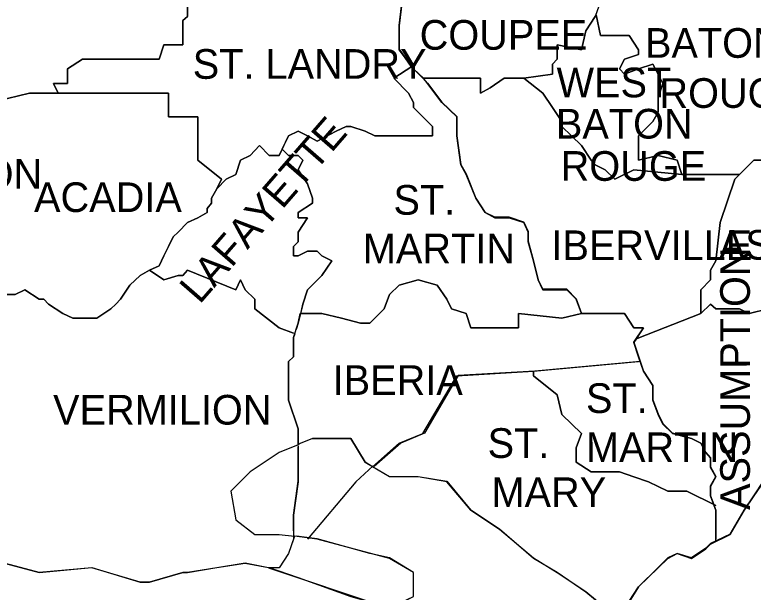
# Model space of a CAD drawing. Extents: x 0.19 to 2.82, y 0.04 to 1.79.
# Drawn here: x 2.3204 to 2.4368, y 1.4533 to 1.5443 of the extents above; entities that cross this region are included whole.
import ezdxf

# ---------------------------------------------------------------- set-up
doc = ezdxf.new("R2010")
doc.units = 0
for name, color, linetype in [('Dist02', 7, 'Continuous'), ('Dist03', 7, 'Continuous'), ('Dist61', 7, 'Continuous'), ('Standard Info', 7, 'Continuous')]:
    doc.layers.add(name, color=color, linetype=linetype)

msp = doc.modelspace()

# ---------------------------------------------------------------- linework, layer by layer
at = {"layer": 'Dist02'}
msp.add_lwpolyline([(2.4369, 1.4685), (2.4354, 1.46625), (2.43315, 1.4625), (2.43007, 1.461), (2.42932, 1.46025), (2.42707, 1.45875), (2.42482, 1.45942), (2.42332, 1.45875), (2.42182, 1.45725), (2.41874, 1.45417), (2.41724, 1.45192), (2.41799, 1.44967), (2.41799, 1.44817), (2.42032, 1.44508), (2.42182, 1.44358), (2.42182, 1.44208), (2.42099, 1.44133), (2.41949, 1.43983), (2.41799, 1.43825), (2.41574, 1.43492)], dxfattribs=at)
at = {"layer": 'Dist03'}
for points in [[(2.3829, 1.53617), (2.38099, 1.53892), (2.38099, 1.54267), (2.38165, 1.548), (2.38165, 1.551), (2.38099, 1.554), (2.37949, 1.55858), (2.3779, 1.56158), (2.37715, 1.56308)], [(2.40974, 1.49725), (2.4089, 1.49958), (2.4074, 1.50108), (2.40365, 1.50108), (2.4029, 1.50258), (2.40215, 1.50558), (2.40132, 1.50867), (2.40132, 1.51017), (2.40065, 1.51167), (2.39832, 1.51242), (2.39607, 1.51242), (2.39457, 1.51317), (2.39307, 1.51542), (2.39157, 1.51925), (2.39074, 1.52075), (2.39007, 1.52525), (2.39007, 1.52833), (2.38774, 1.53058), (2.38549, 1.53358), (2.38474, 1.53433)], [(2.41899, 1.48975), (2.41799, 1.49275), (2.41949, 1.495), (2.41799, 1.495), (2.41649, 1.49725), (2.40974, 1.49725)], [(2.43057, 1.46717), (2.43007, 1.4685), (2.43007, 1.47008), (2.4309, 1.47158), (2.43007, 1.47308), (2.43007, 1.47458), (2.42932, 1.47533), (2.42857, 1.47683), (2.42707, 1.47758), (2.42407, 1.47842), (2.42257, 1.47992), (2.42182, 1.48142), (2.42099, 1.48367), (2.42099, 1.48592), (2.41949, 1.48817), (2.41899, 1.48975)], [(2.36732, 1.47758), (2.3734, 1.47758), (2.37565, 1.47383), (2.37682, 1.47317)], [(2.36432, 1.463), (2.36432, 1.4655), (2.36507, 1.47083), (2.36507, 1.47608), (2.36507, 1.47625)], [(2.37682, 1.47317), (2.37949, 1.47158), (2.38399, 1.47158), (2.38849, 1.47083), (2.39232, 1.46625), (2.39682, 1.46325), (2.40215, 1.45875), (2.4059, 1.45642), (2.4104, 1.45342), (2.41499, 1.44967), (2.41649, 1.44817), (2.41724, 1.44358), (2.41499, 1.44133), (2.41424, 1.43675), (2.41574, 1.435)], [(2.4309, 1.46175), (2.4309, 1.46325), (2.4309, 1.46475), (2.4309, 1.46625), (2.43065, 1.46692)], [(2.36049, 1.45725), (2.36507, 1.45567), (2.3734, 1.45267), (2.37865, 1.45117), (2.38015, 1.45117), (2.38324, 1.45267), (2.38324, 1.45642), (2.37949, 1.45875), (2.3764, 1.45942), (2.36807, 1.46175), (2.36482, 1.46217)], [(2.41574, 1.435), (2.41799, 1.43825), (2.41949, 1.43983), (2.42099, 1.44133), (2.42182, 1.44208), (2.42182, 1.44358), (2.42032, 1.44508), (2.41799, 1.44817), (2.41799, 1.44967), (2.41724, 1.45192), (2.41874, 1.45417), (2.42182, 1.45725), (2.42332, 1.45875), (2.42482, 1.45942), (2.42707, 1.45875), (2.42932, 1.46025), (2.43007, 1.461), (2.43099, 1.46142)], [(2.31815, 1.45808), (2.32424, 1.45642), (2.33257, 1.45725), (2.34015, 1.45492), (2.34165, 1.45492), (2.3469, 1.45642), (2.34765, 1.45642)], [(2.34765, 1.45642), (2.35224, 1.45725), (2.35674, 1.45792), (2.3604, 1.45725)]]:
    msp.add_lwpolyline(points, dxfattribs=at)
at = {"layer": 'Dist61'}
for points in [[(2.37715, 1.56308), (2.3779, 1.56158), (2.37949, 1.55858), (2.38099, 1.554), (2.38165, 1.551), (2.38165, 1.548), (2.38099, 1.54267), (2.38099, 1.53892), (2.3829, 1.53617)], [(2.38299, 1.53617), (2.38324, 1.53583), (2.38482, 1.53433)], [(2.38474, 1.53433), (2.38549, 1.53358), (2.38774, 1.53058), (2.39007, 1.52833), (2.39007, 1.52525), (2.39074, 1.52075), (2.39157, 1.51925), (2.39307, 1.51542), (2.39457, 1.51317), (2.39607, 1.51242), (2.39832, 1.51242), (2.40065, 1.51167), (2.40132, 1.51017), (2.40132, 1.50867), (2.40215, 1.50558), (2.4029, 1.50258), (2.40365, 1.50108), (2.4074, 1.50108), (2.4089, 1.49958), (2.40974, 1.49725)], [(2.40974, 1.49725), (2.41649, 1.49725), (2.41799, 1.495), (2.41949, 1.495), (2.41799, 1.49275), (2.41899, 1.48975)], [(2.41899, 1.48975), (2.41949, 1.48817), (2.42099, 1.48592), (2.42099, 1.48367), (2.42182, 1.48142), (2.42257, 1.47992), (2.42407, 1.47842), (2.42707, 1.47758), (2.42857, 1.47683), (2.42932, 1.47533), (2.43007, 1.47458), (2.43007, 1.47308), (2.4309, 1.47158), (2.43007, 1.47008), (2.43007, 1.4685), (2.43057, 1.46717)], [(2.4309, 1.46133), (2.43315, 1.4625), (2.4354, 1.46625), (2.4369, 1.4685), (2.4384, 1.47083), (2.44065, 1.47458), (2.44215, 1.47683), (2.44215, 1.47908), (2.44299, 1.48067), (2.44524, 1.48292)], [(2.43065, 1.46692), (2.4309, 1.46625), (2.4309, 1.46475), (2.4309, 1.46325), (2.4309, 1.46175)]]:
    msp.add_lwpolyline(points, dxfattribs=at)
at = {"layer": 'Standard Info'}
for p, q in [((2.38482, 1.53433), (2.38474, 1.53433)), ((2.3654, 1.47675), (2.36507, 1.47658)), ((2.43057, 1.46717), (2.4309, 1.467)), ((2.4309, 1.46133), (2.4309, 1.46175))]:
    msp.add_line(p, q, dxfattribs=at)
for points in [[(2.3469, 1.56308), (2.3469, 1.5585), (2.34765, 1.55625), (2.34924, 1.5555), (2.35074, 1.5555), (2.35074, 1.54867), (2.3484, 1.54867), (2.3484, 1.54717), (2.34765, 1.54642), (2.34765, 1.54408), (2.3469, 1.54342), (2.3469, 1.53958), (2.3439, 1.53958), (2.34315, 1.53733), (2.33107, 1.53733), (2.32874, 1.53583), (2.32874, 1.5335), (2.32649, 1.5335), (2.32724, 1.532)], [(2.32724, 1.532), (2.32649, 1.5335), (2.32874, 1.5335), (2.32874, 1.53583), (2.33107, 1.53733), (2.34315, 1.53733), (2.3439, 1.53958), (2.3469, 1.53958), (2.3469, 1.54342), (2.34765, 1.54408), (2.34765, 1.54642), (2.3484, 1.54717), (2.3484, 1.54867), (2.35074, 1.54867), (2.35074, 1.5555), (2.34924, 1.5555), (2.34765, 1.55625), (2.3469, 1.5585), (2.3469, 1.56308)], [(2.37715, 1.56308), (2.3779, 1.5615), (2.37949, 1.5585), (2.38099, 1.554), (2.38165, 1.55092), (2.38165, 1.54792), (2.38099, 1.54258), (2.38099, 1.53883), (2.3829, 1.53617)], [(2.38474, 1.53433), (2.38324, 1.53583), (2.38099, 1.53883), (2.38099, 1.54258), (2.38165, 1.54792), (2.38165, 1.55092), (2.38099, 1.554), (2.37949, 1.5585), (2.3779, 1.5615), (2.37715, 1.56308)], [(2.41274, 1.54642), (2.4119, 1.54408), (2.4104, 1.54183), (2.40974, 1.53883), (2.4059, 1.53958), (2.4059, 1.53733), (2.40515, 1.53658), (2.40515, 1.535), (2.40065, 1.53433)], [(2.40065, 1.53433), (2.40515, 1.535), (2.40515, 1.53658), (2.4059, 1.53733), (2.4059, 1.53958), (2.40974, 1.53883), (2.4104, 1.54183), (2.4119, 1.54408), (2.41199, 1.54433)], [(2.41207, 1.54433), (2.41274, 1.54108), (2.41724, 1.54108), (2.41874, 1.53883), (2.41874, 1.53808), (2.41649, 1.53733), (2.41574, 1.53583), (2.41649, 1.535), (2.41874, 1.53583), (2.42099, 1.53658), (2.42182, 1.535), (2.42257, 1.5335), (2.42182, 1.53125), (2.42182, 1.529), (2.42099, 1.5275), (2.41874, 1.52525), (2.41874, 1.52442), (2.41874, 1.52292), (2.41874, 1.52142), (2.42182, 1.52217), (2.42482, 1.52142), (2.42557, 1.51917)], [(2.42557, 1.51917), (2.42482, 1.52142), (2.42182, 1.52217), (2.41874, 1.52142), (2.41874, 1.52292), (2.41874, 1.52442), (2.41874, 1.52525), (2.42099, 1.5275), (2.42182, 1.529), (2.42182, 1.53125), (2.42257, 1.5335), (2.42182, 1.535), (2.42099, 1.53658), (2.41874, 1.53583), (2.41649, 1.535), (2.41574, 1.53583), (2.41649, 1.53733), (2.41874, 1.53808), (2.41874, 1.53883), (2.41724, 1.54108), (2.41274, 1.54108), (2.41207, 1.54433)], [(2.38299, 1.53617), (2.38015, 1.53433), (2.38249, 1.532), (2.38324, 1.5305), (2.38324, 1.52975), (2.38549, 1.5275), (2.38624, 1.52675), (2.38624, 1.52525), (2.37715, 1.52525), (2.37565, 1.526), (2.3734, 1.52675), (2.37265, 1.52675), (2.37107, 1.526), (2.36807, 1.52442), (2.36657, 1.52525), (2.36507, 1.526), (2.36357, 1.52525), (2.36282, 1.52375), (2.36207, 1.52217), (2.36049, 1.52217), (2.35899, 1.52375), (2.35749, 1.52217), (2.35599, 1.52142), (2.35524, 1.51917), (2.35374, 1.51842), (2.35224, 1.51692)], [(2.36257, 1.52317), (2.36357, 1.52525), (2.36507, 1.526), (2.36657, 1.52525), (2.36807, 1.52442), (2.37107, 1.526), (2.37265, 1.52675), (2.3734, 1.52675), (2.37565, 1.526), (2.37715, 1.52525), (2.38624, 1.52525), (2.38624, 1.52675), (2.38549, 1.5275), (2.38324, 1.52975), (2.38324, 1.5305), (2.38249, 1.532), (2.38015, 1.53433), (2.38299, 1.53617)], [(2.38299, 1.53617), (2.38324, 1.53583), (2.38482, 1.53433)], [(2.38474, 1.53433), (2.38549, 1.5335), (2.38774, 1.5305), (2.39007, 1.52825), (2.39007, 1.52525), (2.39074, 1.52067), (2.39157, 1.51917), (2.39307, 1.51542), (2.39457, 1.51317), (2.39607, 1.51233), (2.39832, 1.51233), (2.40065, 1.51158), (2.40132, 1.51008), (2.40132, 1.50858), (2.40215, 1.50558), (2.4029, 1.50258), (2.40365, 1.501), (2.4074, 1.501), (2.4089, 1.4995), (2.40974, 1.49725)], [(2.40065, 1.53433), (2.39757, 1.53433), (2.39532, 1.53283), (2.39382, 1.532), (2.39382, 1.53433), (2.38474, 1.53433)], [(2.40065, 1.53433), (2.39757, 1.53433), (2.39532, 1.53283), (2.39382, 1.532), (2.39382, 1.53433), (2.38474, 1.53433)], [(2.38474, 1.53433), (2.39382, 1.53433), (2.39382, 1.532), (2.39532, 1.53283), (2.39757, 1.53433), (2.40065, 1.53433)], [(2.4184, 1.49333), (2.41949, 1.495), (2.41799, 1.495), (2.41649, 1.49725), (2.40974, 1.49725), (2.4089, 1.4995), (2.4074, 1.501), (2.40365, 1.501), (2.4029, 1.50258), (2.40215, 1.50558), (2.40132, 1.50858), (2.40132, 1.51008), (2.40065, 1.51158), (2.39832, 1.51233), (2.39607, 1.51233), (2.39457, 1.51317), (2.39307, 1.51542), (2.39157, 1.51917), (2.39074, 1.52067), (2.39007, 1.52525), (2.39007, 1.52825), (2.38774, 1.5305), (2.38549, 1.5335), (2.38482, 1.53433)], [(2.40065, 1.53433), (2.40365, 1.532), (2.40515, 1.52975), (2.40665, 1.5275), (2.40665, 1.52675), (2.40815, 1.52525), (2.40974, 1.52375), (2.41124, 1.52142), (2.4119, 1.52067), (2.41349, 1.51992), (2.41499, 1.51842), (2.41799, 1.51992), (2.42557, 1.51917)], [(2.43465, 1.51917), (2.42557, 1.51917), (2.41799, 1.51992), (2.41499, 1.51842), (2.41349, 1.51992), (2.4119, 1.52067), (2.41124, 1.52142), (2.40974, 1.52375), (2.40815, 1.52525), (2.40665, 1.52675), (2.40665, 1.5275), (2.40515, 1.52975), (2.40365, 1.532), (2.40065, 1.53433)], [(2.40065, 1.53433), (2.40365, 1.532), (2.40515, 1.52975), (2.40665, 1.5275), (2.40665, 1.52675), (2.40815, 1.52525), (2.40974, 1.52375), (2.41124, 1.52142), (2.4119, 1.52067), (2.41349, 1.51992), (2.41499, 1.51842), (2.41799, 1.51992), (2.42557, 1.51917), (2.43465, 1.51917)], [(2.32724, 1.532), (2.32274, 1.532), (2.31749, 1.53075)], [(2.31749, 1.53075), (2.32274, 1.532), (2.32799, 1.532), (2.34465, 1.532), (2.34465, 1.52825), (2.34924, 1.52825), (2.34924, 1.52142), (2.35299, 1.51842), (2.35224, 1.51692)], [(2.35224, 1.51692), (2.35299, 1.51842), (2.34924, 1.52142), (2.34924, 1.52825), (2.34465, 1.52825), (2.34465, 1.532), (2.32724, 1.532)], [(2.34165, 1.50408), (2.34315, 1.50475), (2.3439, 1.50633), (2.34465, 1.50783), (2.3454, 1.50933), (2.34615, 1.51008), (2.34765, 1.51158), (2.34924, 1.51233), (2.35074, 1.51317), (2.35074, 1.51383), (2.3514, 1.51467), (2.3514, 1.51542), (2.35224, 1.51692), (2.35374, 1.51842), (2.35524, 1.51917), (2.35599, 1.52142), (2.35749, 1.52217), (2.35899, 1.52375), (2.36049, 1.52217), (2.36207, 1.52217), (2.36257, 1.52317)], [(2.36257, 1.52317), (2.36357, 1.52217), (2.36507, 1.52217), (2.36582, 1.52142), (2.36507, 1.51992), (2.36657, 1.51767), (2.36732, 1.51542), (2.36732, 1.51467), (2.36507, 1.51317), (2.36507, 1.51233), (2.36657, 1.51233), (2.36507, 1.51008), (2.36507, 1.50858), (2.36432, 1.50783), (2.36432, 1.50633), (2.36507, 1.50633), (2.36657, 1.50708), (2.36807, 1.50708), (2.36882, 1.50633), (2.3704, 1.50558), (2.36882, 1.50325), (2.36657, 1.501), (2.36582, 1.49875), (2.36507, 1.49575), (2.36474, 1.49475)], [(2.36549, 1.49725), (2.36582, 1.49875), (2.36657, 1.501), (2.36882, 1.50325), (2.3704, 1.50558), (2.36882, 1.50633), (2.36807, 1.50708), (2.36657, 1.50708), (2.36507, 1.50633), (2.36432, 1.50633), (2.36432, 1.50783), (2.36507, 1.50858), (2.36507, 1.51008), (2.36657, 1.51233), (2.36507, 1.51233), (2.36507, 1.51317), (2.36732, 1.51467), (2.36732, 1.51542), (2.36657, 1.51767), (2.36507, 1.51992), (2.36582, 1.52142), (2.36507, 1.52217), (2.36357, 1.52217), (2.36257, 1.52317)], [(2.42857, 1.49725), (2.42857, 1.4995), (2.42857, 1.501), (2.43007, 1.50258), (2.43007, 1.50408), (2.4309, 1.50558), (2.43157, 1.51158), (2.4339, 1.51842), (2.4369, 1.52142), (2.44524, 1.52142)], [(2.44524, 1.52142), (2.4369, 1.52142), (2.43465, 1.51917)], [(2.43465, 1.51917), (2.42557, 1.51917)], [(2.43465, 1.51917), (2.4339, 1.51842), (2.43157, 1.51158), (2.4309, 1.50558), (2.43007, 1.50408), (2.43007, 1.50258), (2.42857, 1.501), (2.42857, 1.4995), (2.42857, 1.49725)], [(2.35224, 1.51692), (2.3514, 1.51542), (2.3514, 1.51467), (2.35074, 1.51383), (2.35074, 1.51317), (2.34924, 1.51233), (2.34765, 1.51158), (2.34615, 1.51008), (2.3454, 1.50933), (2.34465, 1.50783), (2.3439, 1.50633), (2.34315, 1.50475), (2.34165, 1.50408), (2.34015, 1.50325), (2.33857, 1.50175), (2.33707, 1.4995), (2.33632, 1.49875), (2.33557, 1.498), (2.33332, 1.4965), (2.33182, 1.4965), (2.32957, 1.4965), (2.32799, 1.49725), (2.32574, 1.49875), (2.32499, 1.4995), (2.32424, 1.4995), (2.32199, 1.501), (2.32049, 1.50025), (2.31765, 1.50025)], [(2.4634, 1.50633), (2.44524, 1.50258), (2.44215, 1.50258), (2.44215, 1.50025), (2.44149, 1.50025), (2.43915, 1.498), (2.43615, 1.49725), (2.43465, 1.498), (2.4339, 1.498), (2.4324, 1.498), (2.4309, 1.498), (2.43007, 1.49875), (2.42857, 1.49725)], [(2.31765, 1.50025), (2.32049, 1.50025), (2.32199, 1.501), (2.32424, 1.4995), (2.32499, 1.4995), (2.32574, 1.49875), (2.32799, 1.49725), (2.32957, 1.4965), (2.33182, 1.4965), (2.33332, 1.4965), (2.33557, 1.498), (2.33632, 1.49875), (2.33707, 1.4995), (2.33857, 1.50175), (2.34015, 1.50325), (2.34165, 1.50408)], [(2.34165, 1.50408), (2.3439, 1.50258), (2.34615, 1.50325), (2.3469, 1.50325), (2.34765, 1.50408), (2.35524, 1.501), (2.35599, 1.50258), (2.35674, 1.501), (2.35824, 1.4995), (2.35824, 1.498), (2.36207, 1.495), (2.36432, 1.49417)], [(2.36432, 1.49417), (2.36207, 1.495), (2.35824, 1.498), (2.35824, 1.4995), (2.35674, 1.501), (2.35599, 1.50258), (2.35524, 1.501), (2.34765, 1.50408), (2.3469, 1.50325), (2.34615, 1.50325), (2.3439, 1.50258), (2.34165, 1.50408)], [(2.36549, 1.49725), (2.36882, 1.49725), (2.3719, 1.4965), (2.3749, 1.49575), (2.3764, 1.49575), (2.3779, 1.49725), (2.37865, 1.498), (2.37949, 1.50025), (2.38099, 1.50175), (2.38399, 1.50258), (2.38699, 1.50175), (2.38849, 1.4995), (2.38924, 1.498), (2.39157, 1.49725), (2.39232, 1.495), (2.39982, 1.495), (2.39982, 1.49725), (2.40665, 1.4965), (2.40974, 1.49725)], [(2.40974, 1.49725), (2.40665, 1.4965), (2.39982, 1.49725), (2.39982, 1.495), (2.39232, 1.495), (2.39157, 1.49725), (2.38924, 1.498), (2.38849, 1.4995), (2.38699, 1.50175), (2.38399, 1.50258), (2.38099, 1.50175), (2.37949, 1.50025), (2.37865, 1.498), (2.3779, 1.49725), (2.3764, 1.49575), (2.3749, 1.49575), (2.3719, 1.4965), (2.36882, 1.49725), (2.36549, 1.49725)], [(2.42857, 1.49725), (2.43007, 1.49875), (2.4309, 1.498), (2.4324, 1.498), (2.4339, 1.498), (2.43465, 1.498), (2.43615, 1.49725), (2.43915, 1.498)], [(2.36507, 1.47658), (2.36507, 1.47908), (2.36357, 1.48358), (2.36357, 1.48967), (2.36432, 1.49042), (2.36432, 1.4935), (2.36507, 1.49575), (2.3654, 1.49725)], [(2.40974, 1.49725), (2.41649, 1.49725), (2.41799, 1.495), (2.41949, 1.495), (2.41799, 1.49267), (2.41899, 1.48967)], [(2.41849, 1.49333), (2.42857, 1.49725)], [(2.42857, 1.49725), (2.41849, 1.49333)], [(2.36457, 1.49408), (2.36432, 1.4935), (2.36432, 1.49042), (2.36357, 1.48967), (2.36357, 1.48358), (2.36507, 1.47908), (2.36507, 1.47658)], [(2.4309, 1.46175), (2.4309, 1.46475), (2.4309, 1.46625), (2.43007, 1.4685), (2.43007, 1.47), (2.4309, 1.4715), (2.43007, 1.473), (2.43007, 1.4745), (2.42932, 1.47533), (2.42857, 1.47683), (2.42707, 1.47758), (2.42407, 1.47833), (2.42257, 1.47983), (2.42182, 1.48133), (2.42099, 1.48358), (2.42099, 1.48592), (2.41949, 1.48817), (2.41874, 1.49042), (2.41799, 1.49267), (2.41849, 1.49333)], [(2.41899, 1.48967), (2.4024, 1.48817), (2.39032, 1.4875), (2.38499, 1.47842), (2.38124, 1.47683), (2.37707, 1.47317)], [(2.40215, 1.48817), (2.41874, 1.48967)], [(2.41899, 1.48975), (2.41949, 1.48817), (2.42099, 1.48592), (2.42099, 1.48358), (2.42182, 1.48133), (2.42257, 1.47983), (2.42407, 1.47833), (2.42707, 1.47758), (2.42857, 1.47683), (2.42932, 1.47533), (2.43007, 1.4745), (2.43007, 1.473), (2.4309, 1.4715), (2.43007, 1.47), (2.43007, 1.4685), (2.43057, 1.46717)], [(2.37682, 1.47308), (2.38099, 1.47683), (2.38474, 1.47833), (2.39007, 1.48742), (2.40215, 1.48817)], [(2.40215, 1.48817), (2.40215, 1.48742), (2.4059, 1.48442), (2.40665, 1.48133), (2.40974, 1.47833), (2.4089, 1.47608), (2.4089, 1.47383), (2.41124, 1.47233), (2.41274, 1.47233), (2.41574, 1.47233), (2.41799, 1.4715), (2.42032, 1.47075), (2.42182, 1.47), (2.42332, 1.46925), (2.42632, 1.46925), (2.4309, 1.467)], [(2.4309, 1.467), (2.42632, 1.46925), (2.42332, 1.46925), (2.42182, 1.47), (2.42032, 1.47075), (2.41799, 1.4715), (2.41574, 1.47233), (2.41274, 1.47233), (2.41124, 1.47233), (2.4089, 1.47383), (2.4089, 1.47608), (2.40974, 1.47833), (2.40665, 1.48133), (2.4059, 1.48442), (2.40215, 1.48742), (2.40215, 1.48817)], [(2.44524, 1.48283), (2.44299, 1.48058), (2.44215, 1.47908), (2.44215, 1.47683), (2.44065, 1.4745), (2.4384, 1.47075), (2.4369, 1.4685), (2.4354, 1.46625), (2.43315, 1.46242), (2.4309, 1.46133)], [(2.36732, 1.47758), (2.3654, 1.47675)], [(2.36732, 1.47758), (2.3654, 1.47675)], [(2.37682, 1.47308), (2.37565, 1.47383), (2.3734, 1.47758), (2.36732, 1.47758)], [(2.37682, 1.47308), (2.37565, 1.47383), (2.3734, 1.47758), (2.36732, 1.47758)], [(2.36507, 1.47658), (2.36207, 1.47533), (2.35749, 1.47233), (2.35449, 1.46925), (2.35524, 1.46475), (2.35824, 1.46242), (2.36207, 1.46242), (2.36449, 1.46217)], [(2.36507, 1.47642), (2.36507, 1.47608), (2.36507, 1.47075), (2.36432, 1.4655), (2.36432, 1.46167), (2.36357, 1.45942), (2.36207, 1.45717), (2.3604, 1.45717)], [(2.3769, 1.47325), (2.37415, 1.47075), (2.36657, 1.46167)], [(2.41574, 1.43492), (2.41424, 1.43675), (2.41499, 1.44125), (2.41724, 1.44358), (2.41649, 1.44808), (2.41499, 1.44958), (2.4104, 1.45333), (2.4059, 1.45642), (2.40215, 1.45867), (2.39682, 1.46325), (2.39232, 1.46625), (2.38849, 1.47075), (2.38399, 1.4715), (2.37949, 1.4715), (2.37682, 1.47308)], [(2.41574, 1.43492), (2.41799, 1.43825), (2.41949, 1.43975), (2.42099, 1.44125), (2.42182, 1.44208), (2.42182, 1.44358), (2.42032, 1.44508), (2.41799, 1.44808), (2.41799, 1.44958), (2.41724, 1.45183), (2.41874, 1.45417), (2.42182, 1.45717), (2.42332, 1.45867), (2.42482, 1.45942), (2.42707, 1.45867), (2.42932, 1.46017), (2.43007, 1.46092), (2.43315, 1.46242), (2.4354, 1.46625), (2.4369, 1.4685)], [(2.43065, 1.46692), (2.4309, 1.46625), (2.4309, 1.46475), (2.4309, 1.46325), (2.4309, 1.46167)], [(2.3604, 1.45717), (2.37865, 1.45108), (2.38015, 1.45108), (2.38324, 1.45267), (2.38324, 1.45642), (2.37949, 1.45867), (2.36807, 1.46167), (2.36449, 1.46217)], [(2.36449, 1.46217), (2.36357, 1.45942), (2.36207, 1.45717), (2.36132, 1.45717)], [(2.43099, 1.46142), (2.43007, 1.46092), (2.42932, 1.46017), (2.42707, 1.45867), (2.42482, 1.45942), (2.42332, 1.45867), (2.42182, 1.45717), (2.41874, 1.45417), (2.41724, 1.45183), (2.41799, 1.44958), (2.41799, 1.44808), (2.42032, 1.44508), (2.42182, 1.44358), (2.42182, 1.44208), (2.42099, 1.44125), (2.41949, 1.43975), (2.41799, 1.43825), (2.41574, 1.43492)], [(2.34765, 1.45642), (2.3469, 1.45642), (2.34165, 1.45492), (2.34015, 1.45492), (2.33257, 1.45717), (2.32424, 1.45642), (2.31815, 1.45808)], [(2.3604, 1.45717), (2.35674, 1.45792), (2.35224, 1.45717), (2.34765, 1.45642)]]:
    msp.add_lwpolyline(points, dxfattribs=at)

# ---------------------------------------------------------------- texts
for s, p in [('COUPEE', (2.38423, 1.53883)), ('BATON', (2.41974, 1.53756)), ('ST. LANDRY', (2.34846, 1.53425)), ('WEST', (2.40581, 1.53133)), ('ROUGE', (2.42202, 1.52967)), ('BATON', (2.4057, 1.52483)), ('ROUGE', (2.40645, 1.51817)), ('JEFFERSON', (2.28754, 1.51692)), ('ACADIA', (2.32345, 1.51325)), ('ST.', (2.3801, 1.51283)), ('MARTIN', (2.37527, 1.50517)), ('IBERVILLE', (2.405, 1.50567)), ('ASCENSION', (2.43137, 1.50575)), ('IBERIA', (2.37051, 1.48442)), ('ST.', (2.41044, 1.48158)), ('VERMILION', (2.32645, 1.47975)), ('ST.', (2.39494, 1.4745)), ('MARTIN', (2.41044, 1.47383)), ('MARY', (2.39555, 1.46675))]:
    msp.add_text(s, height=0.004679, dxfattribs=at).set_placement(p)
for s, height, rotation, p in [('LAFAYETTE', 0.004679, 48.9999, (2.34955, 1.49859)), ('ASSUMPTION', 0.004679, 90.01, (2.43628, 1.4663)), ('G U L F   O F   M E X I C O', 0.0062, 345.6507, (2.26182, 1.4493))]:
    msp.add_text(s, height=height, rotation=rotation, dxfattribs=at).set_placement(p)

doc.saveas('drawing.dxf')
